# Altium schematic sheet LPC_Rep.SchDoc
size A4; Organization: UNSW Solar Racing Team; Address3: UNSW; Address4: Sydney NSW 2052; Address2: Electrical Engineering; Address1: Rm 109
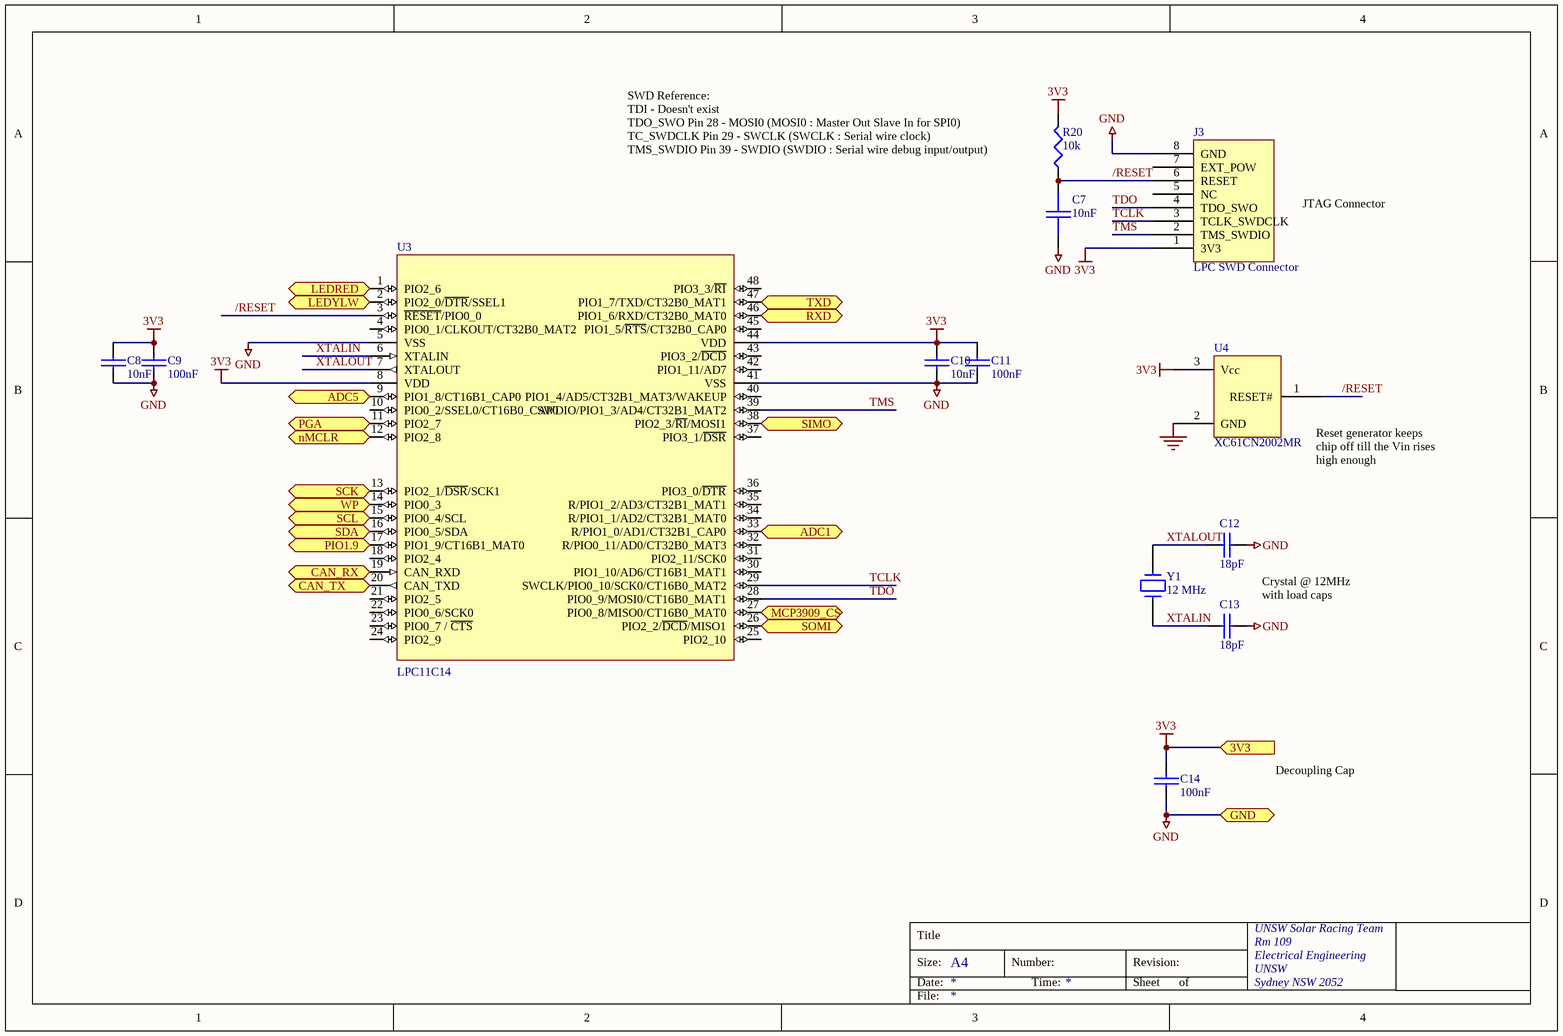
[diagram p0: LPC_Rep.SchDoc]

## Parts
C7  10nF  [0603]
C8  10nF  [0603]
C9  100nF  [0603]
C10  10nF  [0603]
C11  100nF  [0603]
C12  18pF  [0603]
C13  18pF  [0603]
C14  100nF  [0603]
J3  LPC SWD Connector  [IDC8]
R20  10k  [0603]
U3  LPC11C14  [Quad48-LPC11c14]
U4  XC61CN2002MR  [SOT23-3]
Y1  12 MHz  [HC49/4H]

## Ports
3V3, ADC1 (in), ADC5 (in), CAN_RX (in), CAN_TX (out), GND, LEDRED (bidir), LEDYLW (bidir), MCP3909_CS, nMCLR, PGA, PIO1.9 (bidir), RXD (bidir), SCK (bidir), SCL (bidir), SDA (bidir), SIMO (bidir), SOMI (bidir), TXD (bidir), WP (bidir)

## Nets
3V3: C8.2 C9.2 C10.2 C11.2 C14.1 J3.1(3V3) R20.2 U3.8(VDD) U3.44(VDD) U4.3(Vcc) ; port 3V3
GND: C7.2 C8.1 C9.1 C10.1 C11.1 C12.2 C13.2 C14.2 J3.8(GND) U3.5(VSS) U3.41(VSS) U4.2(GND) ; port GND
/RESET: C7.1 J3.6(RESET) R20.1 U3.3(~{RESET}/PIO0_0) U4.1(RESET#)
ADC1: U3.33(R/PIO1_0/AD1/CT32B1_CAP0) ; port ADC1
ADC5: U3.9(PIO1_8/CT16B1_CAP0) ; port ADC5
CAN_RX: U3.19(CAN_RXD) ; port CAN_RX
CAN_TX: U3.20(CAN_TXD) ; port CAN_TX
LEDRED: U3.1(PIO2_6) ; port LEDRED
LEDYLW: U3.2(PIO2_0/~{DTR}/SSEL1) ; port LEDYLW
MCP3909_CS: U3.27(PIO0_8/MISO0/CT16B0_MAT0) ; port MCP3909_CS
nMCLR: U3.12(PIO2_8) ; port nMCLR
PGA: U3.11(PIO2_7) ; port PGA
PIO1.9: U3.17(PIO1_9/CT16B1_MAT0) ; port PIO1.9
RXD: U3.46(PIO1_6/RXD/CT32B0_MAT0) ; port RXD
SCK: U3.13(PIO2_1/~{DSR}/SCK1) ; port SCK
SCL: U3.15(PIO0_4/SCL) ; port SCL
SDA: U3.16(PIO0_5/SDA) ; port SDA
SIMO: U3.38(PIO2_3/~{RI}/MOSI1) ; port SIMO
SOMI: U3.26(PIO2_2/~{DCD}/MISO1) ; port SOMI
TCLK: J3.3(TCLK_SWDCLK) U3.29(SWCLK/PIO0_10/SCK0/CT16B0_MAT2)
TDO: J3.4(TDO_SWO) U3.28(PIO0_9/MOSI0/CT16B0_MAT1)
TMS: J3.2(TMS_SWDIO) U3.39(SWDIO/PIO1_3/AD4/CT32B1_MAT2)
TXD: U3.47(PIO1_7/TXD/CT32B0_MAT1) ; port TXD
WP: U3.14(PIO0_3) ; port WP
XTALIN: C13.1 U3.6(XTALIN) Y1.1
XTALOUT: C12.1 U3.7(XTALOUT) Y1.2

Not connected (* = marked no-connect by the designer): J3 5(NC) 7(EXT_POW); U3 4(PIO0_1/CLKOUT/CT32B0_MAT2) 10(PIO0_2/SSEL0/CT16B0_CAP0) 18(PIO2_4) 21(PIO2_5) 22(PIO0_6/SCK0) 23(PIO0_7_/_~{CTS}) 24(PIO2_9) 25(PIO2_10) 30(PIO1_10/AD6/CT16B1_MAT1) 31(PIO2_11/SCK0) 32(R/PIO0_11/AD0/CT32B0_MAT3) 34(R/PIO1_1/AD2/CT32B1_MAT0) 35(R/PIO1_2/AD3/CT32B1_MAT1) 36(PIO3_0/~{DTR}) 37(PIO3_1/~{DSR}) 40(PIO1_4/AD5/CT32B1_MAT3/WAKEUP) 42(PIO1_11/AD7) 43(PIO3_2/~{DCD}) 45(PIO1_5/~{RTS}/CT32B0_CAP0) 48(PIO3_3/~{RI})

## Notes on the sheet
- SWD Reference:
  TDI - Doesn't exist
  TDO_SWO Pin 28 - MOSI0 (MOSI0 : Master Out Slave In for SPI0)
  TC_SWDCLK Pin 29 - SWCLK (SWCLK : Serial wire clock)
  TMS_SWDIO Pin 39 - SWDIO (SWDIO : Serial wire debug input/output)
- JTAG Connector
- (near U4) Reset generator keeps chip off till the Vin rises high enough
- Crystal @ 12MHz with load caps
- Decoupling Cap

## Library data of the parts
C7-C14 = CAP: Capacitor
J3 = LPCLink_Connector
R20 = RES1: Resistor
U3 = LPC11C14_Full
U4 = XC61F: SOT23 reset generator
Y1 = CRYSTAL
